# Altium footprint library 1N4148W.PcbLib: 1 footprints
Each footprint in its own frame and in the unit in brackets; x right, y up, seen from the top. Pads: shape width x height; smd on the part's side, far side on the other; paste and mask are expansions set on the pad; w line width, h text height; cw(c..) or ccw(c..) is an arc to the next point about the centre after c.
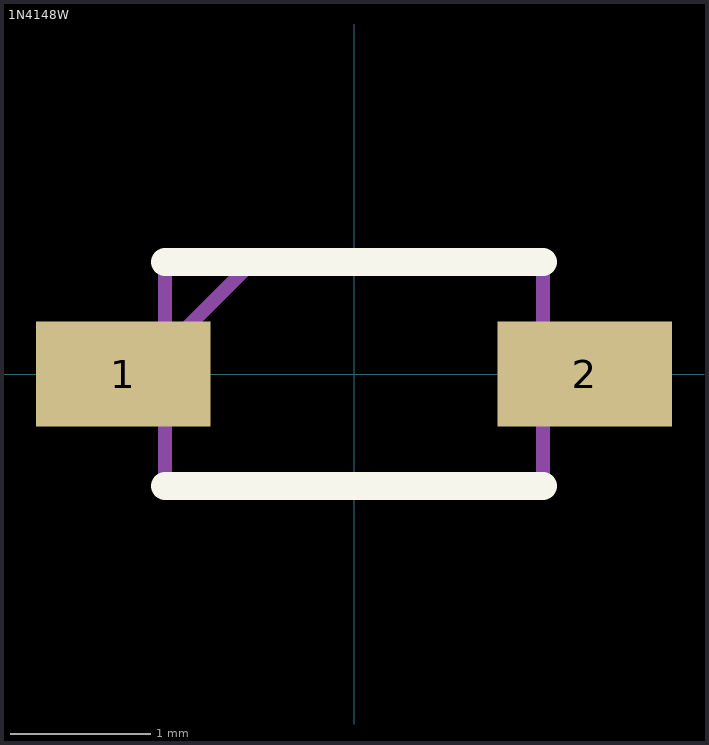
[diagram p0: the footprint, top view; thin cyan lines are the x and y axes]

## 1N4148W [mm]
pads (2):
  rect 1.25x0.75 smd: 1(-1.65,0) 2(1.65,0)
Top Overlay:
  lines w0.2: -1.35,-0.8 1.35,-0.8 ; -1.35,0.8 1.35,0.8
Mechanical 13:
  lines w0.1: -1.35,0.175 -0.725,0.8 ; -1.35,-0.8 -1.35,0.8 1.35,0.8 1.35,-0.8 -1.35,-0.8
